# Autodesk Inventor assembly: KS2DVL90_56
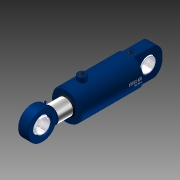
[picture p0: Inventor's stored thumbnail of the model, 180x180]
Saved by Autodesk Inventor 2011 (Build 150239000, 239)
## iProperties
Created: 2010-11
Document SubType Name: Assembly
Designer: TB
Mass: 566.294 g
Surface Area: 1153.75 cm^2
Volume: 566.294 cm^3
Density: 1 g/cm^3
Description: KS2DVL 90/56 - 100 mm
Slaglengde: 100,000 mm
Author: TB
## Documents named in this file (6)
- C:\Vault\Sylinderteknikk\Projects_ST\3D.nettkatalog\KS2-Series\KS2DVL\KS2DVL90_56\KS2DVL90_56.iam
- C:\Vault\Sylinderteknikk\Projects_ST\3D.nettkatalog\KS2-Series\KS2DVL\KS2DVL90_56\KS2DVL90_56_stang.ipt
- C:\Vault\Sylinderteknikk\Projects_ST\3D.nettkatalog\KS2-Series\KS2DVL\KS2DVL90_56\KS2DVL90_56_Parameters.ipt
- C:\Vault\Sylinderteknikk\Projects_ST\3D.nettkatalog\KS2-Series\KS2DVL\KS2DVL90_56\KS2DVL90_56_body..ipt
- C:\Vault\Sylinderteknikk\Imported Components\27-7785-03\Part40.ipt
- C:\Vault\Sylinderteknikk\Projects_ST\Øyer\Klinkby.KS.Øyer\KS.45.eye.komplett\KS.45.Eye.Komplett.ipt
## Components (5 placed, 5 different names)
1. KS2DVL90_56_Parameters:3
2. KS2DVL90_56_stang:1 — Mate:1, FriMate:2, Mate:3, Insert:3
3. KS2DVL90_56_body.:1 — Mate:1, FriMate:2, Mate:3, Insert:2, Angle:1
4. Part40:1 — Insert:2
5. KS.45.Eye.Komplett:1 — Insert:3, Angle:1
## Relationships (6: Mate 3, Insert 2, Angle 1)
- Mate:1: KS2DVL90_56_stang:1 ↔ KS2DVL90_56_body.:1
- FriMate:2 [Mate]: KS2DVL90_56_stang:1 ↔ KS2DVL90_56_body.:1
- Mate:3: KS2DVL90_56_stang:1 ↔ KS2DVL90_56_body.:1
- Insert:2: KS2DVL90_56_body.:1 ↔ Part40:1
- Insert:3: KS2DVL90_56_stang:1 ↔ KS.45.Eye.Komplett:1
- Angle:1: KS2DVL90_56_body.:1 ↔ KS.45.Eye.Komplett:1
## Named parameters: Forlengelse_rør = 0, Vinkel_Minusport = 0
